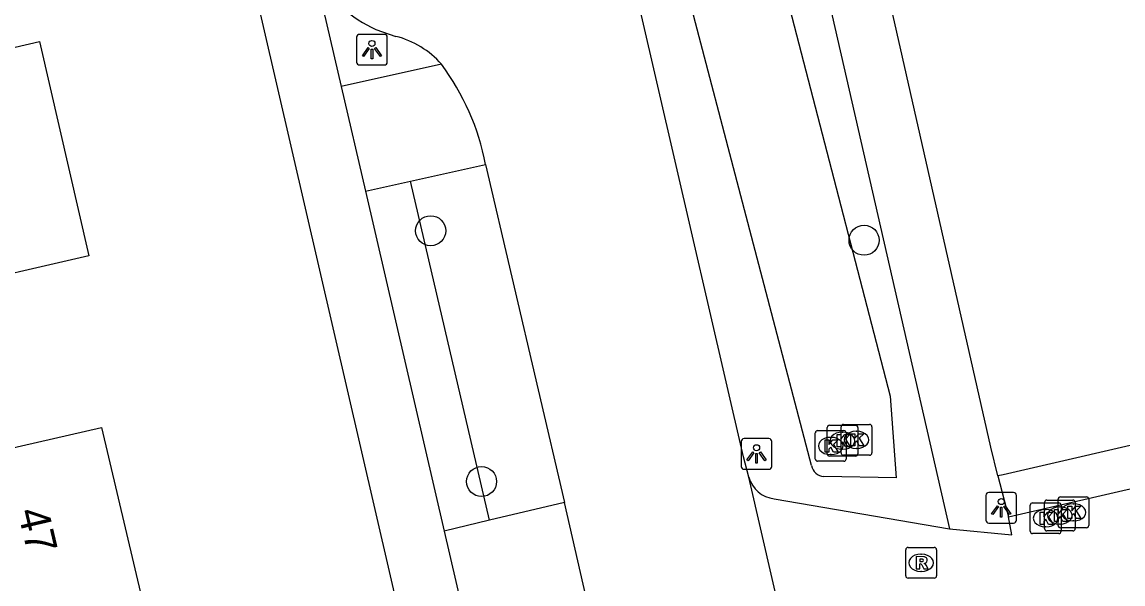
# Model space of a CAD drawing. Extents: x 156414 to 157775, y 382335 to 383765.
# Drawn here: x 156659.19 to 156694.98, y 382866.65 to 382884.93 of the extents above; entities that cross this region are included whole.
import ezdxf

# ---------------------------------------------------------------- set-up
doc = ezdxf.new("R2010")
doc.units = 0
for name, color, linetype in [('IMGEO_Boom', 7, 'Continuous'), ('IMGEO_Greppel_droge_sloot', 7, 'Continuous'), ('IMGEO_Kolk', 7, 'Continuous'), ('IMGEO_Lichtpunt', 7, 'Continuous'), ('IMGEO_Pand', 7, 'Continuous'), ('IMGEO_Pand_nummerreeks', 7, 'Continuous'), ('IMGEO_Parkeervlak_open', 7, 'Continuous'), ('IMGEO_Rijbaan_lokaal_gesloten', 7, 'Continuous'), ('IMGEO_Rijbaan_lokaal_open', 7, 'Continuous'), ('IMGEO_Rioolput', 7, 'Continuous'), ('IMGEO_Voetpad_open', 7, 'Continuous')]:
    doc.layers.add(name, color=color, linetype=linetype)

msp = doc.modelspace()

# ---------------------------------------------------------------- linework, layer by layer
at = {"layer": 'IMGEO_Boom'}
for centre in [(156672.472, 382878.143), (156686.561, 382877.834), (156674.125, 382869.984)]:
    msp.add_circle(centre, 0.489, dxfattribs=at)
at = {"layer": 'IMGEO_Greppel_droge_sloot'}
for points in [[(156681.618, 382895.117), (156687.407, 382872.758), (156687.607, 382870.105), (156685.253, 382870.145)], [(156684.85, 382870.502), (156678.6, 382894.402)]]:
    msp.add_lwpolyline(points, dxfattribs=at)
msp.add_arc((156685.289, 382870.591), 0.448, 191.4982, 265.4292, dxfattribs=at)
at = {"layer": 'IMGEO_Kolk'}
for p, q in [((156685.362, 382870.887), (156685.362, 382871.739)), ((156685.437, 382871.813), (156686.289, 382871.813)), ((156685.814, 382870.915), (156685.814, 382871.767)), ((156685.889, 382871.841), (156686.741, 382871.841)), ((156686.363, 382871.739), (156686.363, 382870.887)), ((156686.815, 382871.767), (156686.815, 382870.915)), ((156684.977, 382870.716), (156684.977, 382871.568)), ((156685.052, 382871.642), (156685.904, 382871.642)), ((156685.465, 382871.422), (156685.49, 382871.422)), ((156685.85, 382871.593), (156685.875, 382871.593)), ((156685.978, 382871.568), (156685.978, 382870.716)), ((156686.302, 382871.621), (156686.327, 382871.621)), ((156685.873, 382871.033), (156685.848, 382871.033)), ((156686.325, 382871.061), (156686.3, 382871.061)), ((156685.904, 382870.642), (156685.052, 382870.642)), ((156686.289, 382870.813), (156685.437, 382870.813)), ((156685.488, 382870.862), (156685.463, 382870.862)), ((156686.741, 382870.841), (156685.889, 382870.841)), ((156691.964, 382868.364), (156691.964, 382869.216)), ((156692.039, 382869.29), (156692.891, 382869.29)), ((156692.427, 382868.452), (156692.427, 382869.304)), ((156692.502, 382869.378), (156693.354, 382869.378)), ((156692.868, 382868.556), (156692.868, 382869.408)), ((156692.943, 382869.482), (156693.795, 382869.482)), ((156692.965, 382869.216), (156692.965, 382868.364)), ((156693.356, 382869.262), (156693.381, 382869.262)), ((156693.428, 382869.304), (156693.428, 382868.452)), ((156693.869, 382869.408), (156693.869, 382868.556)), ((156692.452, 382869.07), (156692.477, 382869.07)), ((156692.915, 382869.158), (156692.94, 382869.158)), ((156692.475, 382868.51), (156692.45, 382868.51)), ((156692.938, 382868.598), (156692.913, 382868.598)), ((156693.379, 382868.702), (156693.354, 382868.702)), ((156692.891, 382868.29), (156692.039, 382868.29)), ((156693.354, 382868.378), (156692.502, 382868.378)), ((156693.795, 382868.482), (156692.943, 382868.482))]:
    msp.add_line(p, q, dxfattribs=at)
for points in [[(156685.362, 382870.887), (156685.362, 382871.739)], [(156685.437, 382871.813), (156686.289, 382871.813)], [(156685.814, 382870.915), (156685.814, 382871.767)], [(156685.889, 382871.841), (156686.741, 382871.841)], [(156686.363, 382871.739), (156686.363, 382870.887)], [(156686.815, 382871.767), (156686.815, 382870.915)], [(156684.977, 382870.716), (156684.977, 382871.568)], [(156685.052, 382871.642), (156685.904, 382871.642)], [(156685.683, 382871.513), (156685.806, 382871.513), (156685.806, 382871.362), (156685.936, 382871.513), (156686.1, 382871.513), (156685.954, 382871.362), (156686.107, 382871.113), (156685.955, 382871.113), (156685.87, 382871.277), (156685.806, 382871.21), (156685.806, 382871.113), (156685.683, 382871.113), (156685.683, 382871.513)], [(156685.978, 382871.568), (156685.978, 382870.716)], [(156686.135, 382871.541), (156686.258, 382871.541), (156686.258, 382871.39), (156686.388, 382871.541), (156686.552, 382871.541), (156686.406, 382871.39), (156686.559, 382871.141), (156686.407, 382871.141), (156686.322, 382871.305), (156686.258, 382871.238), (156686.258, 382871.141), (156686.135, 382871.141), (156686.135, 382871.541)], [(156685.298, 382871.342), (156685.421, 382871.342), (156685.421, 382871.191), (156685.551, 382871.342), (156685.715, 382871.342), (156685.569, 382871.191), (156685.722, 382870.942), (156685.57, 382870.942), (156685.485, 382871.106), (156685.421, 382871.039), (156685.421, 382870.942), (156685.298, 382870.942), (156685.298, 382871.342)], [(156685.904, 382870.642), (156685.052, 382870.642)], [(156686.289, 382870.813), (156685.437, 382870.813)], [(156686.741, 382870.841), (156685.889, 382870.841)], [(156691.964, 382868.364), (156691.964, 382869.216)], [(156692.039, 382869.29), (156692.891, 382869.29)], [(156692.427, 382868.452), (156692.427, 382869.304)], [(156692.502, 382869.378), (156693.354, 382869.378)], [(156692.868, 382868.556), (156692.868, 382869.408)], [(156692.943, 382869.482), (156693.795, 382869.482)], [(156692.965, 382869.216), (156692.965, 382868.364)], [(156693.428, 382869.304), (156693.428, 382868.452)], [(156693.869, 382869.408), (156693.869, 382868.556)], [(156692.285, 382868.99), (156692.408, 382868.99), (156692.408, 382868.839), (156692.538, 382868.99), (156692.702, 382868.99), (156692.556, 382868.839), (156692.709, 382868.59), (156692.557, 382868.59), (156692.472, 382868.754), (156692.408, 382868.687), (156692.408, 382868.59), (156692.285, 382868.59), (156692.285, 382868.99)], [(156692.748, 382869.078), (156692.871, 382869.078), (156692.871, 382868.927), (156693.001, 382869.078), (156693.165, 382869.078), (156693.019, 382868.927), (156693.172, 382868.678), (156693.02, 382868.678), (156692.935, 382868.842), (156692.871, 382868.775), (156692.871, 382868.678), (156692.748, 382868.678), (156692.748, 382869.078)], [(156693.189, 382869.182), (156693.312, 382869.182), (156693.312, 382869.031), (156693.442, 382869.182), (156693.606, 382869.182), (156693.46, 382869.031), (156693.613, 382868.782), (156693.461, 382868.782), (156693.376, 382868.946), (156693.312, 382868.879), (156693.312, 382868.782), (156693.189, 382868.782), (156693.189, 382869.182)], [(156692.891, 382868.29), (156692.039, 382868.29)], [(156693.354, 382868.378), (156692.502, 382868.378)], [(156693.795, 382868.482), (156692.943, 382868.482)]]:
    msp.add_lwpolyline(points, dxfattribs=at)
for centre, start, end in [((156685.439, 382871.737), 91.552, 178.448), ((156685.439, 382871.737), 91.552, 178.448), ((156685.891, 382871.765), 91.552, 178.448), ((156685.891, 382871.765), 91.552, 178.448), ((156686.287, 382871.737), 1.552, 88.448), ((156686.287, 382871.737), 1.552, 88.448), ((156686.739, 382871.765), 1.552, 88.448), ((156686.739, 382871.765), 1.552, 88.448), ((156685.054, 382871.566), 91.552, 178.448), ((156685.054, 382871.566), 91.552, 178.448), ((156685.902, 382871.566), 1.552, 88.448), ((156685.902, 382871.566), 1.552, 88.448), ((156685.054, 382870.718), 181.552, 268.448), ((156685.054, 382870.718), 181.552, 268.448), ((156685.439, 382870.889), 181.552, 268.448), ((156685.439, 382870.889), 181.552, 268.448), ((156685.891, 382870.917), 181.552, 268.448), ((156685.891, 382870.917), 181.552, 268.448), ((156685.902, 382870.718), 271.552, 358.448), ((156685.902, 382870.718), 271.552, 358.448), ((156686.287, 382870.889), 271.552, 358.448), ((156686.287, 382870.889), 271.552, 358.448), ((156686.739, 382870.917), 271.552, 358.448), ((156686.739, 382870.917), 271.552, 358.448), ((156692.041, 382869.214), 91.552, 178.448), ((156692.041, 382869.214), 91.552, 178.448), ((156692.504, 382869.302), 91.552, 178.448), ((156692.504, 382869.302), 91.552, 178.448), ((156692.945, 382869.406), 91.552, 178.448), ((156692.945, 382869.406), 91.552, 178.448), ((156692.889, 382869.214), 1.552, 88.448), ((156692.889, 382869.214), 1.552, 88.448), ((156693.352, 382869.302), 1.552, 88.448), ((156693.352, 382869.302), 1.552, 88.448), ((156693.793, 382869.406), 1.552, 88.448), ((156693.793, 382869.406), 1.552, 88.448), ((156692.945, 382868.558), 181.552, 268.448), ((156692.945, 382868.558), 181.552, 268.448), ((156693.793, 382868.558), 271.552, 358.448), ((156693.793, 382868.558), 271.552, 358.448), ((156692.041, 382868.366), 181.552, 268.448), ((156692.041, 382868.366), 181.552, 268.448), ((156692.504, 382868.454), 181.552, 268.448), ((156692.504, 382868.454), 181.552, 268.448), ((156692.889, 382868.366), 271.552, 358.448), ((156692.889, 382868.366), 271.552, 358.448), ((156693.352, 382868.454), 271.552, 358.448), ((156693.352, 382868.454), 271.552, 358.448)]:
    msp.add_arc(centre, 0.0765, start, end, dxfattribs=at)
for centre, major_axis, ratio, start_param, end_param in [((156685.464, 382871.142), (-0.387, 0.002), 0.722429, 4.712389, 7.853982), ((156685.849, 382871.313), (-0.387, 0.002), 0.722429, 4.712389, 7.853982), ((156685.489, 382871.142), (-0.39, 0.002), 0.717154, 1.570796, 4.712389), ((156685.874, 382871.313), (-0.39, 0.002), 0.717154, 1.570796, 4.712389), ((156686.301, 382871.341), (-0.387, 0.002), 0.722429, 4.712389, 7.853982), ((156686.326, 382871.341), (-0.39, 0.002), 0.717154, 1.570796, 4.712389), ((156693.355, 382868.982), (-0.387, 0.002), 0.722429, 4.712389, 7.853982), ((156693.38, 382868.982), (-0.39, 0.002), 0.717154, 1.570796, 4.712389), ((156692.451, 382868.79), (-0.387, 0.002), 0.722429, 4.712389, 7.853982), ((156692.476, 382868.79), (-0.39, 0.002), 0.717154, 1.570796, 4.712389), ((156692.914, 382868.878), (-0.387, 0.002), 0.722429, 4.712389, 7.853982), ((156692.939, 382868.878), (-0.39, 0.002), 0.717154, 1.570796, 4.712389)]:
    msp.add_ellipse(centre, major_axis=major_axis, ratio=ratio, start_param=start_param, end_param=end_param, dxfattribs=at)
at = {"layer": 'IMGEO_Lichtpunt'}
for p, q in [((156670.063, 382884.438), (156670.063, 382883.631)), ((156670.063, 382884.438), (156670.063, 382883.631)), ((156670.965, 382884.533), (156670.157, 382884.533)), ((156670.965, 382884.533), (156670.157, 382884.533)), ((156671.059, 382883.631), (156671.059, 382884.438)), ((156671.059, 382883.631), (156671.059, 382884.438)), ((156670.157, 382883.537), (156670.965, 382883.537)), ((156670.157, 382883.537), (156670.965, 382883.537)), ((156683.468, 382871.38), (156682.66, 382871.38)), ((156683.468, 382871.38), (156682.66, 382871.38)), ((156682.566, 382871.285), (156682.566, 382870.478)), ((156682.566, 382871.285), (156682.566, 382870.478)), ((156683.562, 382870.478), (156683.562, 382871.285)), ((156683.562, 382870.478), (156683.562, 382871.285)), ((156682.66, 382870.384), (156683.468, 382870.384)), ((156682.66, 382870.384), (156683.468, 382870.384)), ((156691.423, 382869.629), (156690.615, 382869.629)), ((156691.423, 382869.629), (156690.615, 382869.629)), ((156690.521, 382869.534), (156690.521, 382868.727)), ((156690.521, 382869.534), (156690.521, 382868.727)), ((156691.517, 382868.727), (156691.517, 382869.534)), ((156691.517, 382868.727), (156691.517, 382869.534)), ((156690.615, 382868.633), (156691.423, 382868.633)), ((156690.615, 382868.633), (156691.423, 382868.633))]:
    msp.add_line(p, q, dxfattribs=at)
for points in [[(156670.437, 382884.102), (156670.476, 382884.074), (156670.288, 382883.812), (156670.25, 382883.839), (156670.437, 382884.102)], [(156670.539, 382884.054), (156670.586, 382884.054), (156670.586, 382883.732), (156670.539, 382883.732), (156670.539, 382884.054)], [(156670.649, 382884.074), (156670.687, 382884.101), (156670.874, 382883.839), (156670.835, 382883.811), (156670.649, 382884.074)], [(156682.94, 382870.949), (156682.979, 382870.921), (156682.791, 382870.659), (156682.753, 382870.686), (156682.94, 382870.949)], [(156683.042, 382870.901), (156683.089, 382870.901), (156683.089, 382870.579), (156683.042, 382870.579), (156683.042, 382870.901)], [(156683.152, 382870.921), (156683.19, 382870.948), (156683.377, 382870.686), (156683.338, 382870.658), (156683.152, 382870.921)], [(156690.895, 382869.198), (156690.934, 382869.17), (156690.746, 382868.908), (156690.708, 382868.935), (156690.895, 382869.198)], [(156690.997, 382869.15), (156691.044, 382869.15), (156691.044, 382868.828), (156690.997, 382868.828), (156690.997, 382869.15)], [(156691.107, 382869.17), (156691.145, 382869.197), (156691.332, 382868.935), (156691.293, 382868.907), (156691.107, 382869.17)]]:
    msp.add_lwpolyline(points, dxfattribs=at)
for centre in [(156670.562, 382884.236), (156683.065, 382871.083), (156691.02, 382869.332)]:
    msp.add_circle(centre, 0.0994, dxfattribs=at)
for centre, start, end in [((156670.157, 382884.438), 90, 180), ((156670.157, 382884.438), 90, 180), ((156670.965, 382884.438), 0, 90), ((156670.965, 382884.438), 0, 90), ((156670.157, 382883.631), 180, 270), ((156670.157, 382883.631), 180, 270), ((156670.965, 382883.631), 270, 0), ((156670.965, 382883.631), 270, 360), ((156682.66, 382871.285), 90, 180), ((156682.66, 382871.285), 90, 180), ((156683.468, 382871.285), 0, 90), ((156683.468, 382871.285), 0, 90), ((156682.66, 382870.478), 180, 270), ((156682.66, 382870.478), 180, 270), ((156683.468, 382870.478), 270, 0), ((156683.468, 382870.478), 270, 360), ((156690.615, 382869.534), 90, 180), ((156690.615, 382869.534), 90, 180), ((156691.423, 382869.534), 0, 90), ((156691.423, 382869.534), 0, 90), ((156690.615, 382868.727), 180, 270), ((156690.615, 382868.727), 180, 270), ((156691.423, 382868.727), 270, 0), ((156691.423, 382868.727), 270, 360)]:
    msp.add_arc(centre, 0.0946, start, end, dxfattribs=at)
at = {"layer": 'IMGEO_Pand'}
for points in [[(156647.271, 382874.069), (156645.666, 382881.009), (156648.189, 382881.593), (156647.19, 382885.623), (156654.192, 382887.871), (156655.257, 382883.262), (156656.621, 382883.577), (156659.759, 382884.302), (156661.361, 382877.323), (156647.271, 382874.069)], [(156654.036, 382860.733), (156651.124, 382860.071), (156649.135, 382868.845), (156661.768, 382871.742), (156663.076, 382866.177), (156658.283, 382865.065), (156658.912, 382862.15), (156658.974, 382861.865), (156654.036, 382860.733)]]:
    msp.add_lwpolyline(points, dxfattribs=at)
at = {"layer": 'IMGEO_Parkeervlak_open'}
msp.add_lwpolyline([(156674.387, 382868.723), (156671.817, 382879.757)], dxfattribs=at)
at = {"layer": 'IMGEO_Rijbaan_lokaal_gesloten'}
for points in [[(156682.815, 382870.13), (156682.646, 382870.787), (156677.074, 382894.919), (156673.903, 382894.251)], [(156670.69, 382884.695), (156671.342, 382884.468)], [(156674.258, 382880.299), (156676.82, 382869.3)], [(156685.565, 382858.168), (156682.815, 382870.13)], [(156677.608, 382865.89), (156676.82, 382869.3)]]:
    msp.add_lwpolyline(points, dxfattribs=at)
for centre, radius, start, end in [((156672.529, 382888.782), 4.481, 212.1352, 245.7756), ((156670.62, 382881.634), 2.924, 41.241, 75.7086), ((156666.371, 382878.77), 8.034, 10.9741, 36.6214)]:
    msp.add_arc(centre, radius, start, end, dxfattribs=at)
at = {"layer": 'IMGEO_Rijbaan_lokaal_open'}
for points in [[(156691.253, 382868.836), (156764.262, 382885.667), (156910.514, 382919.415)], [(156672.819, 382883.562), (156669.561, 382882.832)], [(156669.561, 382882.832), (156670.354, 382879.432)], [(156671.817, 382879.757), (156674.258, 382880.299)], [(156670.354, 382879.432), (156671.817, 382879.757)], [(156676.82, 382869.3), (156674.387, 382868.723)], [(156683.638, 382869.423), (156689.34, 382868.448)], [(156674.387, 382868.723), (156672.905, 382868.372)], [(156689.34, 382868.448), (156691.37, 382868.246), (156691.253, 382868.836)], [(156672.905, 382868.372), (156673.696, 382864.956)]]:
    msp.add_lwpolyline(points, dxfattribs=at)
msp.add_arc((156683.742, 382870.377), 0.96, 194.909, 263.7624, dxfattribs=at)
at = {"layer": 'IMGEO_Rioolput'}
for p, q in [((156687.992, 382867.84), (156688.844, 382867.84)), ((156687.917, 382866.914), (156687.917, 382867.766)), ((156688.405, 382867.62), (156688.43, 382867.62)), ((156688.918, 382867.766), (156688.918, 382866.914)), ((156688.428, 382867.06), (156688.403, 382867.06)), ((156688.844, 382866.84), (156687.992, 382866.84))]:
    msp.add_line(p, q, dxfattribs=at)
for points in [[(156687.992, 382867.84), (156688.844, 382867.84)], [(156687.917, 382866.914), (156687.917, 382867.766)], [(156688.506, 382867.538), (156688.254, 382867.54), (156688.254, 382867.14)], [(156688.432, 382867.459), (156688.378, 382867.459), (156688.378, 382867.378)], [(156688.918, 382867.766), (156688.918, 382866.914)], [(156688.254, 382867.14), (156688.378, 382867.14), (156688.378, 382867.302), (156688.389, 382867.302)], [(156688.378, 382867.378), (156688.43, 382867.378)], [(156688.436, 382867.273), (156688.507, 382867.14), (156688.647, 382867.14), (156688.582, 382867.266)], [(156688.844, 382866.84), (156687.992, 382866.84)]]:
    msp.add_lwpolyline(points, dxfattribs=at)
for centre, radius, start, end in [((156687.994, 382867.764), 0.0765, 91.552, 178.448), ((156687.994, 382867.764), 0.0765, 91.552, 178.448), ((156688.842, 382867.764), 0.0765, 1.552, 88.448), ((156688.842, 382867.764), 0.0765, 1.552, 88.448), ((156688.438, 382867.363), 0.0964, 77.0061, 93.1865), ((156688.452, 382867.42), 0.0378, 276.6634, 79.6772), ((156688.505, 382867.428), 0.109, 350.3612, 89.416), ((156688.503, 382867.428), 0.112, 277.5842, 350.9817), ((156688.388, 382867.249), 0.0533, 26.0293, 88.6989), ((156688.414, 382867.567), 0.19, 274.7715, 282.9687), ((156688.487, 382867.213), 0.108, 29.5134, 73.7905), ((156687.994, 382866.916), 0.0765, 181.552, 268.448), ((156687.994, 382866.916), 0.0765, 181.552, 268.448), ((156688.842, 382866.916), 0.0765, 271.552, 358.448), ((156688.842, 382866.916), 0.0765, 271.552, 358.448)]:
    msp.add_arc(centre, radius, start, end, dxfattribs=at)
for centre, major_axis, ratio, start_param, end_param in [((156688.404, 382867.34), (-0.387, 0.002), 0.722429, 4.712389, 7.853982), ((156688.429, 382867.34), (-0.39, 0.002), 0.717154, 1.570796, 4.712389)]:
    msp.add_ellipse(centre, major_axis=major_axis, ratio=ratio, start_param=start_param, end_param=end_param, dxfattribs=at)
at = {"layer": 'IMGEO_Voetpad_open'}
for points in [[(156682.265, 382899.418), (156689.34, 382868.448)], [(156694.882, 382764.275), (156665.21, 382892.732)], [(156764.886, 382887.169), (156763.167, 382886.771), (156752.267, 382884.266), (156749.132, 382883.546), (156746.584, 382882.96), (156743.001, 382882.137), (156737.32, 382880.831), (156733.737, 382880.008), (156728.086, 382878.709), (156724.482, 382877.881), (156718.817, 382876.579), (156715.202, 382875.748), (156709.554, 382874.45), (156705.981, 382873.629), (156700.308, 382872.325), (156696.761, 382871.51), (156691.087, 382870.206), (156690.913, 382870.166)], [(156668.734, 382886.398), (156669.561, 382882.832)], [(156690.913, 382870.166), (156690.683, 382871.101), (156687.498, 382885.175)], [(156670.354, 382879.432), (156672.905, 382868.372)], [(156690.913, 382870.166), (156691.253, 382868.836)]]:
    msp.add_lwpolyline(points, dxfattribs=at)

# ---------------------------------------------------------------- texts
at = {"layer": 'IMGEO_Pand_nummerreeks'}
msp.add_text('47', height=1, rotation=283.2267, dxfattribs=at).set_placement((156659.04, 382869.014))

doc.saveas('drawing.dxf')
